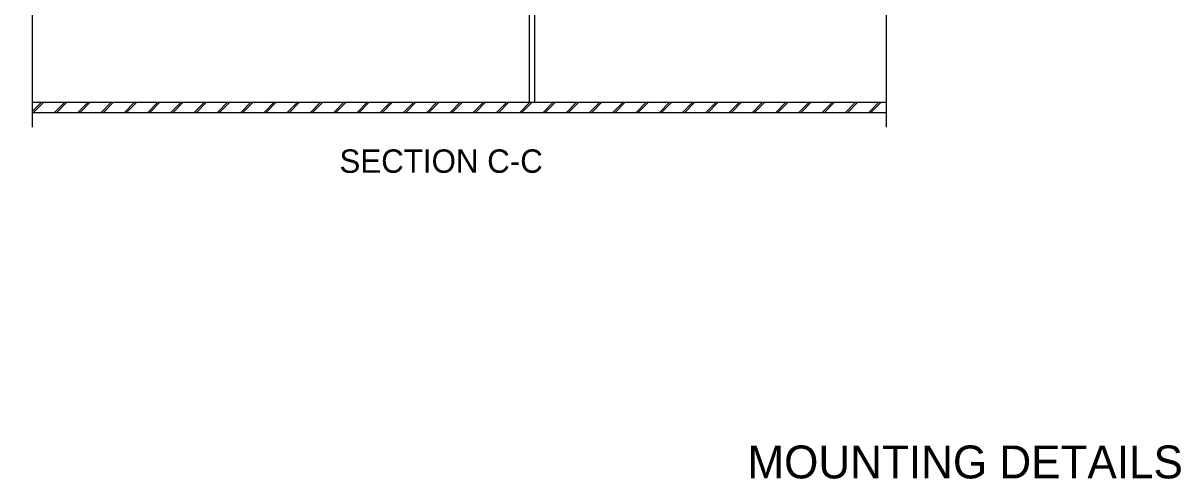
# Model space of a CAD drawing. Extents: x 927736.2 to 927809.6, y 636703.6 to 636757.7.
# Drawn here: x 927786.14 to 927809.58, y 636705.98 to 636715.22 of the extents above; entities that cross this region are included whole.
import ezdxf

# ---------------------------------------------------------------- set-up
doc = ezdxf.new("R2010")
doc.units = 0
for name, color, linetype in [('Default', 7, 'Continuous'), ('DimLines_dp', 7, 'Continuous'), ('Miscellaneous3', 7, 'Continuous'), ('TextMisc', 7, 'Continuous')]:
    doc.layers.add(name, color=color, linetype=linetype)

msp = doc.modelspace()

# ---------------------------------------------------------------- linework, layer by layer
at = {"layer": 'DimLines_dp'}
for points in [[(927786.333, 636713.104), (927786.333, 636722.378), (927786.142, 636722.378), (927786.333, 636722.461), (927786.524, 636722.544), (927786.333, 636722.544), (927786.333, 636731.807)], [(927803.622, 636713.104), (927803.622, 636722.378), (927803.431, 636722.378), (927803.622, 636722.461), (927803.813, 636722.544), (927803.622, 636722.544), (927803.622, 636724.526)]]:
    msp.add_lwpolyline(points, dxfattribs=at)
at = {"layer": 'Miscellaneous3'}
for p, q in [((927796.389, 636715.462), (927796.389, 636713.612)), ((927796.492, 636715.462), (927796.492, 636713.612)), ((927786.333, 636713.612), (927803.622, 636713.612)), ((927786.333, 636713.431), (927786.514, 636713.612)), ((927786.352, 636713.407), (927786.557, 636713.612)), ((927786.779, 636713.407), (927786.985, 636713.612)), ((927786.823, 636713.407), (927787.028, 636713.612)), ((927787.25, 636713.407), (927787.456, 636713.612)), ((927787.294, 636713.407), (927787.499, 636713.612)), ((927787.721, 636713.407), (927787.926, 636713.612)), ((927787.765, 636713.407), (927787.97, 636713.612)), ((927788.192, 636713.407), (927788.397, 636713.612)), ((927788.236, 636713.407), (927788.441, 636713.612)), ((927788.663, 636713.407), (927788.868, 636713.612)), ((927788.707, 636713.407), (927788.912, 636713.612)), ((927789.134, 636713.407), (927789.339, 636713.612)), ((927789.177, 636713.407), (927789.383, 636713.612)), ((927789.605, 636713.407), (927789.81, 636713.612)), ((927789.648, 636713.407), (927789.854, 636713.612)), ((927790.076, 636713.407), (927790.281, 636713.612)), ((927790.119, 636713.407), (927790.325, 636713.612)), ((927790.547, 636713.407), (927790.752, 636713.612)), ((927790.59, 636713.407), (927790.796, 636713.612)), ((927791.018, 636713.407), (927791.223, 636713.612)), ((927791.061, 636713.407), (927791.267, 636713.612)), ((927791.489, 636713.407), (927791.694, 636713.612)), ((927791.532, 636713.407), (927791.738, 636713.612)), ((927791.959, 636713.407), (927792.165, 636713.612)), ((927792.003, 636713.407), (927792.208, 636713.612)), ((927792.43, 636713.407), (927792.636, 636713.612)), ((927792.474, 636713.407), (927792.679, 636713.612)), ((927792.901, 636713.407), (927793.107, 636713.612)), ((927792.945, 636713.407), (927793.15, 636713.612)), ((927793.372, 636713.407), (927793.578, 636713.612)), ((927793.416, 636713.407), (927793.621, 636713.612)), ((927793.843, 636713.407), (927794.049, 636713.612)), ((927793.887, 636713.407), (927794.092, 636713.612)), ((927794.314, 636713.407), (927794.52, 636713.612)), ((927794.358, 636713.407), (927794.563, 636713.612)), ((927794.785, 636713.407), (927794.99, 636713.612)), ((927794.829, 636713.407), (927795.034, 636713.612)), ((927795.256, 636713.407), (927795.461, 636713.612)), ((927795.3, 636713.407), (927795.505, 636713.612)), ((927795.727, 636713.407), (927795.932, 636713.612)), ((927795.771, 636713.407), (927795.976, 636713.612)), ((927796.198, 636713.407), (927796.403, 636713.612)), ((927796.241, 636713.407), (927796.447, 636713.612)), ((927796.669, 636713.407), (927796.874, 636713.612)), ((927796.712, 636713.407), (927796.918, 636713.612)), ((927797.14, 636713.407), (927797.345, 636713.612)), ((927797.183, 636713.407), (927797.389, 636713.612)), ((927797.611, 636713.407), (927797.816, 636713.612)), ((927797.654, 636713.407), (927797.86, 636713.612)), ((927798.082, 636713.407), (927798.287, 636713.612)), ((927798.125, 636713.407), (927798.331, 636713.612)), ((927798.553, 636713.407), (927798.758, 636713.612)), ((927798.596, 636713.407), (927798.802, 636713.612)), ((927799.023, 636713.407), (927799.229, 636713.612)), ((927799.067, 636713.407), (927799.272, 636713.612)), ((927799.494, 636713.407), (927799.7, 636713.612)), ((927799.538, 636713.407), (927799.743, 636713.612)), ((927799.965, 636713.407), (927800.171, 636713.612)), ((927800.009, 636713.407), (927800.214, 636713.612)), ((927800.436, 636713.407), (927800.642, 636713.612)), ((927800.48, 636713.407), (927800.685, 636713.612)), ((927800.907, 636713.407), (927801.113, 636713.612)), ((927800.951, 636713.407), (927801.156, 636713.612)), ((927801.378, 636713.407), (927801.584, 636713.612)), ((927801.422, 636713.407), (927801.627, 636713.612)), ((927801.849, 636713.407), (927802.055, 636713.612)), ((927801.893, 636713.407), (927802.098, 636713.612)), ((927802.32, 636713.407), (927802.525, 636713.612)), ((927802.364, 636713.407), (927802.569, 636713.612)), ((927802.791, 636713.407), (927802.996, 636713.612)), ((927802.835, 636713.407), (927803.04, 636713.612)), ((927803.262, 636713.407), (927803.467, 636713.612)), ((927803.306, 636713.407), (927803.511, 636713.612)), ((927786.333, 636713.407), (927803.622, 636713.407))]:
    msp.add_line(p, q, dxfattribs=at)

# ---------------------------------------------------------------- texts
at = {"layer": 'Default'}
msp.add_text('SECTION C-C', height=0.4736, dxfattribs=at).set_placement((927792.546, 636712.182))
at = {"layer": 'TextMisc'}
msp.add_text('       MOUNTING DETAILS        ', height=0.66664, dxfattribs=at).set_placement((927799.072, 636705.988))

doc.saveas('drawing.dxf')
